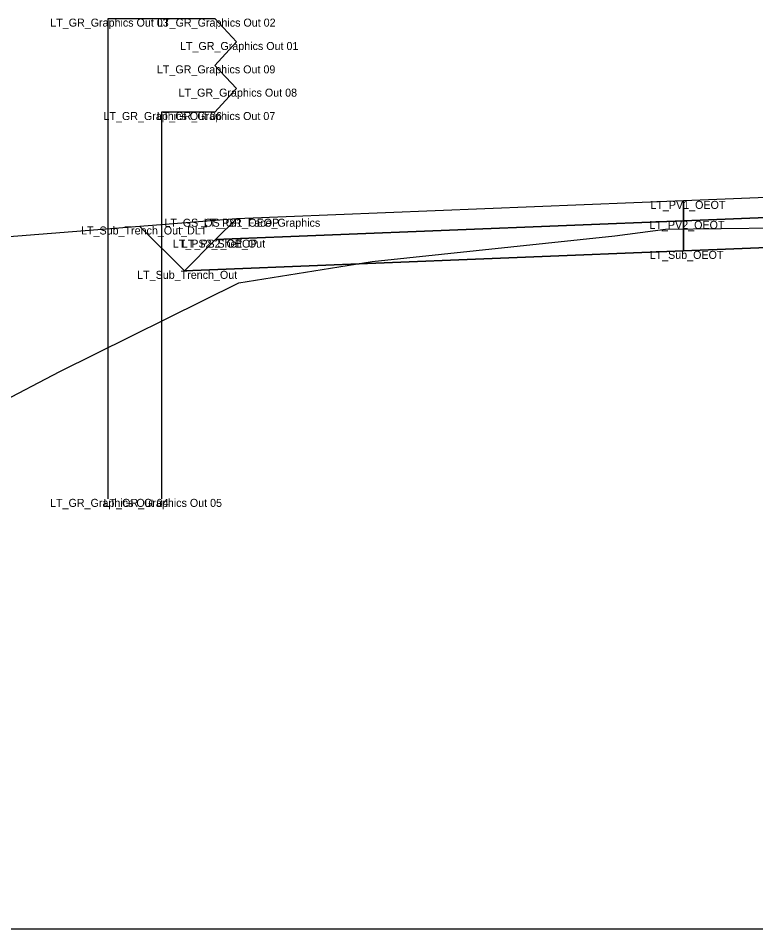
# Model space of a CAD drawing. Extents: x -26 to 203, y -10 to 20020.
# Drawn here: x 80.69 to 89.9, y 4000 to 4011.38 of the extents above; entities that cross this region are included whole.
import ezdxf

# ---------------------------------------------------------------- set-up
doc = ezdxf.new("R2010")
doc.units = 0
for name, color, linetype in [('Default', 7, 'Continuous'), ('Exist Cross Section Cell', 7, 'Continuous'), ('Exist XS Ground Line', 7, 'Continuous'), ('Prop CMT Guardrail Graphics', 7, 'Continuous'), ('Prop CMT Pvmt Course 1', 7, 'Continuous'), ('Prop CMT Pvmt Course 2', 7, 'Continuous'), ('Prop CMT Pvmt Surface', 7, 'Continuous'), ('Prop CMT Pvmt Surface Shoulder', 7, 'Continuous'), ('Prop CMT Shld Paved Course 1', 7, 'Continuous'), ('Prop CMT Shld Paved Course 2', 7, 'Continuous'), ('Prop CMT Slope Grass', 7, 'Continuous'), ('Prop CMT Subgrade Earthwork', 7, 'Continuous')]:
    doc.layers.add(name, color=color, linetype=linetype)

msp = doc.modelspace()

# ---------------------------------------------------------------- linework, layer by layer
at = {"layer": 'Exist Cross Section Cell'}
msp.add_line((0, 4000), (100, 4000), dxfattribs=at)
at = {"layer": 'Exist XS Ground Line'}
for p, q in [((88.143, 4008.656), (88.774, 4008.742)), ((88.774, 4008.742), (92.819, 4008.792)), ((85.11, 4008.338), (88.143, 4008.656)), ((83.446, 4008.071), (85.11, 4008.338)), ((81.209, 4006.963), (83.446, 4008.071)), ((75.159, 4003.784), (81.209, 4006.963))]:
    msp.add_line(p, q, dxfattribs=at)
at = {"layer": 'Prop CMT Guardrail Graphics'}
for points in [[(81.813, 4005.371), (81.813, 4011.371)], [(81.813, 4011.371), (83.146, 4011.371), (83.417, 4011.079)], [(83.417, 4011.079), (83.146, 4010.787)], [(83.146, 4010.787), (83.417, 4010.496)], [(83.417, 4010.496), (83.146, 4010.204), (82.479, 4010.204)], [(82.479, 4010.204), (82.479, 4005.371)]]:
    msp.add_lwpolyline(points, dxfattribs=at)
at = {"layer": 'Prop CMT Pvmt Course 1'}
for points in [[(100, 4009.534), (89, 4009.094)], [(89, 4008.844), (100, 4009.284)], [(89, 4009.094), (89, 4008.844)]]:
    msp.add_lwpolyline(points, dxfattribs=at)
at = {"layer": 'Prop CMT Pvmt Course 2'}
for points in [[(100, 4009.284), (89, 4008.844)], [(89, 4008.469), (100, 4008.909)], [(89, 4008.844), (89, 4008.469)]]:
    msp.add_lwpolyline(points, dxfattribs=at)
at = {"layer": 'Prop CMT Pvmt Surface'}
msp.add_lwpolyline([(100, 4009.534), (89, 4009.094)], dxfattribs=at)
at = {"layer": 'Prop CMT Pvmt Surface Shoulder'}
msp.add_lwpolyline([(89, 4009.094), (83.417, 4008.871)], dxfattribs=at)
at = {"layer": 'Prop CMT Shld Paved Course 1'}
for points in [[(89, 4009.094), (83.417, 4008.871), (83.156, 4008.61)], [(89, 4008.844), (89, 4009.094)], [(83.156, 4008.61), (89, 4008.844)]]:
    msp.add_lwpolyline(points, dxfattribs=at)
at = {"layer": 'Prop CMT Shld Paved Course 2'}
for points in [[(89, 4008.844), (83.156, 4008.61)], [(89, 4008.469), (89, 4008.844)], [(83.156, 4008.61), (82.766, 4008.22)], [(83.156, 4008.61), (83.156, 4008.61)], [(82.766, 4008.22), (89, 4008.469)]]:
    msp.add_lwpolyline(points, dxfattribs=at)
at = {"layer": 'Prop CMT Slope Grass'}
for points in [[(83.417, 4008.871), (80, 4008.597)], [(83.417, 4008.871), (83.417, 4008.871)]]:
    msp.add_lwpolyline(points, dxfattribs=at)
at = {"layer": 'Prop CMT Subgrade Earthwork'}
for points in [[(100, 4008.909), (89, 4008.469)], [(82.766, 4008.22), (82.211, 4008.774)], [(89, 4008.469), (82.766, 4008.22)]]:
    msp.add_lwpolyline(points, dxfattribs=at)

# ---------------------------------------------------------------- texts
at = {"layer": 'Default'}
for s, p in [('LT_GR_Graphics Out 03', (81.091, 4011.271)), ('LT_GR_Graphics Out 02', (82.426, 4011.271)), ('LT_GR_Graphics Out 01', (82.711, 4010.979)), ('LT_GR_Graphics Out 09', (82.423, 4010.687)), ('LT_GR_Graphics Out 08', (82.694, 4010.396)), ('LT_GR_Graphics Out 06', (81.756, 4010.104)), ('LT_GR_Graphics Out 07', (82.422, 4010.104)), ('LT_PV1_OEOT', (88.587, 4008.994)), ('LT_GS_OS_GR_Face_Graphics', (82.516, 4008.771)), ('LT_PS1_OEOP', (83.007, 4008.771)), ('LT_PV2_OEOT', (88.575, 4008.744)), ('LT_Sub_Trench_Out_DLT', (81.476, 4008.674)), ('LT_PS2_Shelf_Out', (82.622, 4008.51)), ('LT_PS2_OEOP', (82.735, 4008.51)), ('LT_Sub_OEOT', (88.577, 4008.369)), ('LT_Sub_Trench_Out', (82.177, 4008.12)), ('LT_GR_Graphics Out 04', (81.089, 4005.271)), ('LT_GR_Graphics Out 05', (81.757, 4005.271))]:
    msp.add_text(s, height=0.1, dxfattribs=at).set_placement(p)

doc.saveas('drawing.dxf')
